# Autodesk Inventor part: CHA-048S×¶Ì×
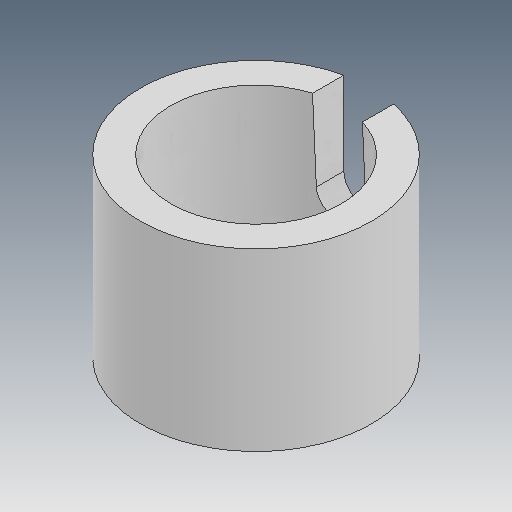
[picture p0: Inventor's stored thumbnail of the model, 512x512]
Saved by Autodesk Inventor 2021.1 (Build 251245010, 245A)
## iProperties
Created: 2019-12
Part Number: CHA-048S×¶Ì×
Material: Ogólny
Document SubType Name: Modeling
Designer: user
Density: 1 g/cm^3
Appearance: Domyślna
Author: user
Revision Number: ÈÎºÎ
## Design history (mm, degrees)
feature "ÊäÈë1"
node "Bryła1"
